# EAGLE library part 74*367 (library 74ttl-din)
Hex BUS DRIVER, 3-state
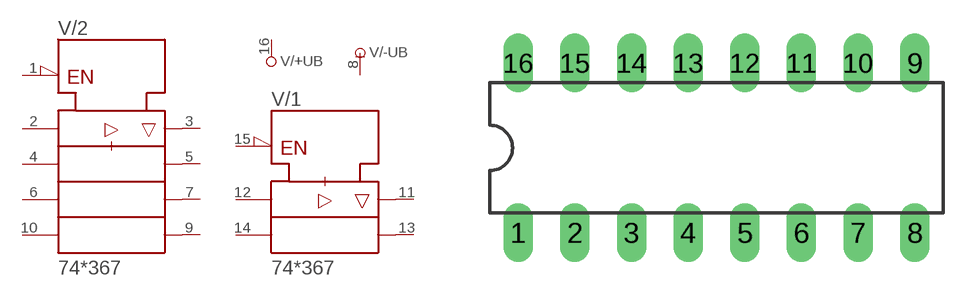
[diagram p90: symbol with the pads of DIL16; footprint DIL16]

Designator prefix V; gates /+UB=+UB /-UB=-UB /1=367_2 /2=367_1

## 74367N  [DIL16]
1  /2:G\  in
2  /2:A1  in
3  /2:Y1  hiz
4  /2:A2  in
5  /2:Y2  hiz
6  /2:A3  in
7  /2:Y3  hiz
8  /-UB:-UB  pwr
9  /2:Y4  hiz
10  /2:A4  in
11  /1:Y1  hiz
12  /1:A1  in
13  /1:Y2  hiz
14  /1:A2  in
15  /1:G\  in
16  /+UB:+UB  pwr

## Footprint DIL16 (pad centres in mm)
Dual In Line Package
drill 0.813 long: 1 -8.89,-3.81; 2 -6.35,-3.81; 3 -3.81,-3.81; 4 -1.27,-3.81; 5 1.27,-3.81; 6 3.81,-3.81; 7 6.35,-3.81; 8 8.89,-3.81; 9 8.89,3.81; 10 6.35,3.81; 11 3.81,3.81; 12 1.27,3.81; 13 -1.27,3.81; 14 -3.81,3.81; 15 -6.35,3.81; 16 -8.89,3.81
